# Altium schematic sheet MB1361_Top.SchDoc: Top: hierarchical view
size A4; Date: Not used; ApprovedBy: Not used; CheckedBy: Not used; Author: Not used; CompanyName: STMicroelectronics; DrawnBy: Not used; Engineer: Not used; Organization: Not used; Address1: Not used; Address2: Not used; Address3: Not used; Address4: Not used; DocumentNumber: 2; Revision: A-01-P3; SheetNumber: 2; SheetTotal: 9
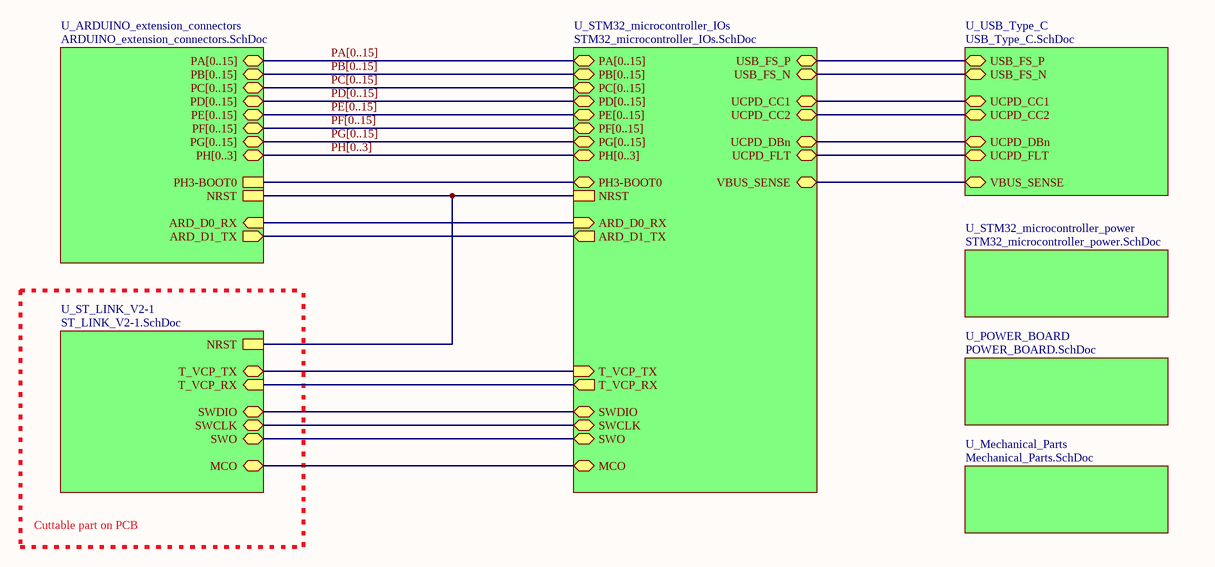
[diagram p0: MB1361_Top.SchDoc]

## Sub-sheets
U_ARDUINO_extension_connectors = ARDUINO_extension_connectors.SchDoc: PA[0..15] (bidir), PB[0..15] (bidir), PC[0..15] (bidir), NRST, PH3-BOOT0, PD[0..15] (bidir), PE[0..15] (bidir), PF[0..15] (bidir), PG[0..15] (bidir), PH[0..3] (bidir), ARD_D0_RX (in), ARD_D1_TX (out)
U_Mechanical_Parts = Mechanical_Parts.SchDoc: no entries
U_POWER_BOARD = POWER_BOARD.SchDoc: no entries
U_ST_LINK_V2-1 = ST_LINK_V2-1.SchDoc: NRST, SWO, SWCLK, MCO, SWDIO, T_VCP_TX, T_VCP_RX (in)
U_STM32_microcontroller_IOs = STM32_microcontroller_IOs.SchDoc: NRST, PA[0..15] (bidir), PB[0..15] (bidir), PC[0..15] (bidir), PD[0..15] (bidir), PE[0..15] (bidir), USB_FS_N (bidir), USB_FS_P (bidir), PF[0..15] (bidir), PG[0..15] (bidir), PH[0..3] (bidir), PH3-BOOT0, ARD_D0_RX (in), ARD_D1_TX (out), SWO, MCO, SWCLK, SWDIO, VBUS_SENSE, T_VCP_RX (out), T_VCP_TX (in), UCPD_CC2 (bidir), UCPD_CC1 (bidir), UCPD_FLT, UCPD_DBn
U_STM32_microcontroller_power = STM32_microcontroller_power.SchDoc: no entries
U_USB_Type_C = USB_Type_C.SchDoc: USB_FS_N (bidir), USB_FS_P (bidir), VBUS_SENSE, UCPD_CC1 (bidir), UCPD_CC2 (bidir), UCPD_DBn, UCPD_FLT

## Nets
(unnamed): sheet U_STM32_microcontroller_IOs/NRST, sheet U_ST_LINK_V2-1/NRST, sheet U_ARDUINO_extension_connectors/NRST
(unnamed): sheet U_STM32_microcontroller_IOs/USB_FS_N, sheet U_USB_Type_C/USB_FS_N  [a separate net that carries the same name]
(unnamed): sheet U_STM32_microcontroller_IOs/USB_FS_P, sheet U_USB_Type_C/USB_FS_P  [a separate net that carries the same name]
(unnamed): sheet U_STM32_microcontroller_IOs/PH3-BOOT0, sheet U_ARDUINO_extension_connectors/PH3-BOOT0  [a separate net that carries the same name]
(unnamed): sheet U_STM32_microcontroller_IOs/ARD_D0_RX, sheet U_ARDUINO_extension_connectors/ARD_D0_RX  [a separate net that carries the same name]
(unnamed): sheet U_STM32_microcontroller_IOs/ARD_D1_TX, sheet U_ARDUINO_extension_connectors/ARD_D1_TX  [a separate net that carries the same name]
(unnamed): sheet U_STM32_microcontroller_IOs/SWO, sheet U_ST_LINK_V2-1/SWO  [a separate net that carries the same name]
(unnamed): sheet U_STM32_microcontroller_IOs/MCO, sheet U_ST_LINK_V2-1/MCO  [a separate net that carries the same name]
(unnamed): sheet U_STM32_microcontroller_IOs/SWCLK, sheet U_ST_LINK_V2-1/SWCLK  [a separate net that carries the same name]
(unnamed): sheet U_STM32_microcontroller_IOs/SWDIO, sheet U_ST_LINK_V2-1/SWDIO  [a separate net that carries the same name]
(unnamed): sheet U_STM32_microcontroller_IOs/VBUS_SENSE, sheet U_USB_Type_C/VBUS_SENSE  [a separate net that carries the same name]
(unnamed): sheet U_STM32_microcontroller_IOs/T_VCP_RX, sheet U_ST_LINK_V2-1/T_VCP_RX  [a separate net that carries the same name]
(unnamed): sheet U_STM32_microcontroller_IOs/T_VCP_TX, sheet U_ST_LINK_V2-1/T_VCP_TX  [a separate net that carries the same name]
(unnamed): sheet U_STM32_microcontroller_IOs/UCPD_CC2, sheet U_USB_Type_C/UCPD_CC2  [a separate net that carries the same name]
(unnamed): sheet U_STM32_microcontroller_IOs/UCPD_CC1, sheet U_USB_Type_C/UCPD_CC1  [a separate net that carries the same name]
(unnamed): sheet U_STM32_microcontroller_IOs/UCPD_FLT, sheet U_USB_Type_C/UCPD_FLT  [a separate net that carries the same name]
(unnamed): sheet U_STM32_microcontroller_IOs/UCPD_DBn, sheet U_USB_Type_C/UCPD_DBn  [a separate net that carries the same name]

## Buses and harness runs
bus PA[0..15] = sheet U_ARDUINO_extension_connectors/PA[0..15] = sheet U_STM32_microcontroller_IOs/PA[0..15]
bus PB[0..15] = sheet U_ARDUINO_extension_connectors/PB[0..15] = sheet U_STM32_microcontroller_IOs/PB[0..15]
bus PC[0..15] = sheet U_ARDUINO_extension_connectors/PC[0..15] = sheet U_STM32_microcontroller_IOs/PC[0..15]
bus PD[0..15] = sheet U_ARDUINO_extension_connectors/PD[0..15] = sheet U_STM32_microcontroller_IOs/PD[0..15]
bus PE[0..15] = sheet U_ARDUINO_extension_connectors/PE[0..15] = sheet U_STM32_microcontroller_IOs/PE[0..15]
bus PF[0..15] = sheet U_ARDUINO_extension_connectors/PF[0..15] = sheet U_STM32_microcontroller_IOs/PF[0..15]
bus PG[0..15] = sheet U_ARDUINO_extension_connectors/PG[0..15] = sheet U_STM32_microcontroller_IOs/PG[0..15]
bus PH[0..3] = sheet U_ARDUINO_extension_connectors/PH[0..3] = sheet U_STM32_microcontroller_IOs/PH[0..3]

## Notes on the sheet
- Cuttable part on PCB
